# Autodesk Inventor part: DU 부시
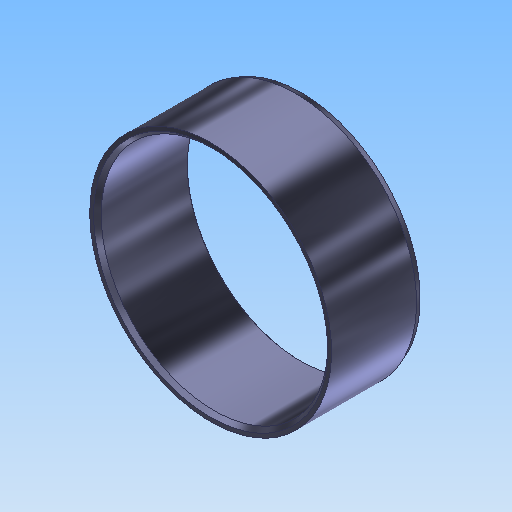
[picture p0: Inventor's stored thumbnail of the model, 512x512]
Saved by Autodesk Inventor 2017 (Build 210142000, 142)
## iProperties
Created: 2023-11
Part Number: DU 부시
Material: 강철, 합금
Document SubType Name: Modeling
Designer: mdu-01
Density: 1 g/cm^3
Appearance: 반광택(1)
Author: mdu-01
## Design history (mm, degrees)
sketch "스케치1"
  geometry: L1 (0, 0)-(0, -30); L2 (38.75, 0)-(40, 0); L3 (40, 0)-(40, -28.125); L4 (39.318, -30)-(37.75, -30); L5 (37.5, -29.75)-(37.5, -1.25); L6 (38.75, 0)-(37.5, -1.25); L7 (40, -28.125)-(39.318, -30); L8 (37.75, -30)-(37.5, -29.75); 3 further points
  constraints: 16 end point, 8 point on line, 2 parallel, 1 horizontal, 1 perpendicular, 1 vertical
  dimensions: "d0" = 30 distance of L1.start L1.end; "d1" = 1.25 distance of L2.start point (37.5, 0); "d2" = 1.25 distance of L5.end point (37.5, 0) (= d1); "d3" = 1.875 distance of L3.end point (40, -30); "d4" = 20 deg angle of L3 L7; "d5" = 0.25 distance of L4.end point (37.5, -30); "d6" = 0.25 distance of L5.start point (37.5, -30) (= d5); "d7" = 75 diameter of L5 L1; "d8" = 80 diameter of L3 L1
revolve "회전1" sketch "스케치1" stored, may be unused: angle "d9" = 90 deg
node "솔리드1"
